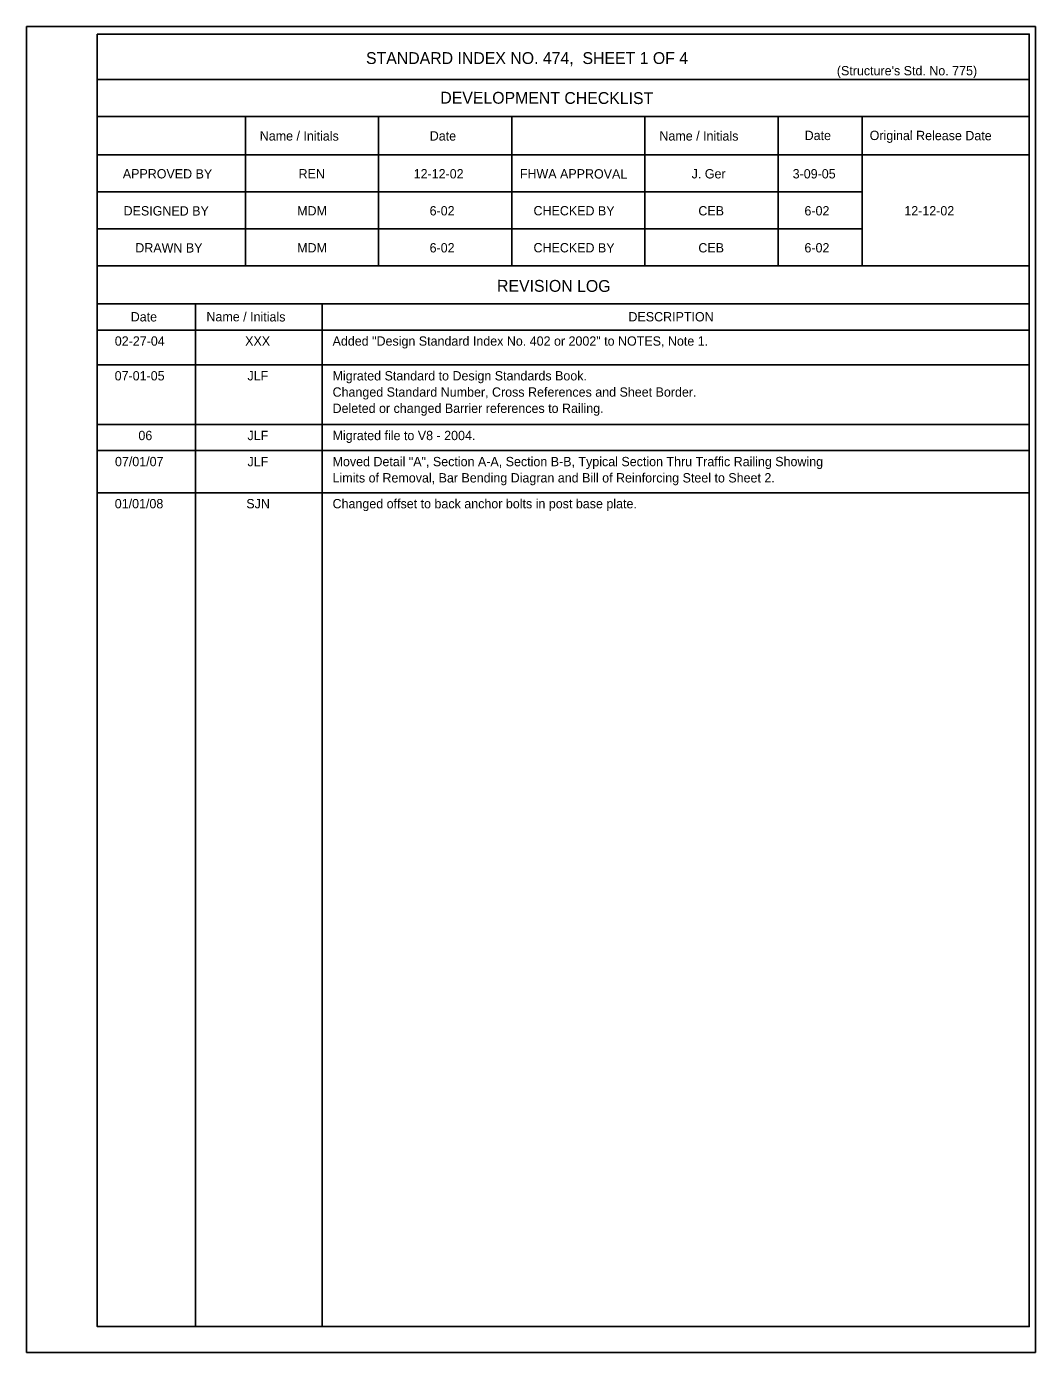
# Model space of a CAD drawing. Extents: x 21629.5 to 21698.8, y 56199.1 to 56237.6.
# Drawn here: x 21677.04 to 21698.85, y 56206.43 to 56235.1 of the extents above; entities that cross this region are included whole.
import ezdxf

# ---------------------------------------------------------------- set-up
doc = ezdxf.new("R2010")
doc.units = 0
for name, color, linetype in [('Border', 7, 'Continuous'), ('Dimension', 7, 'Continuous'), ('PlotBorder_dp', 7, 'Continuous'), ('TextStructures', 7, 'Continuous')]:
    doc.layers.add(name, color=color, linetype=linetype)

msp = doc.modelspace()

# ---------------------------------------------------------------- linework, layer by layer
at = {"layer": 'Border'}
for p, q in [((21698.712, 56233.957), (21678.566, 56233.957)), ((21698.712, 56233.157), (21678.566, 56233.157)), ((21681.766, 56233.157), (21681.766, 56229.929)), ((21684.646, 56233.157), (21684.646, 56229.929)), ((21687.526, 56233.157), (21687.526, 56229.929)), ((21690.406, 56233.157), (21690.406, 56229.929)), ((21693.286, 56233.157), (21693.286, 56229.929)), ((21695.101, 56233.157), (21695.101, 56229.929)), ((21698.712, 56232.329), (21678.566, 56232.329)), ((21695.101, 56231.529), (21678.566, 56231.529)), ((21695.101, 56230.729), (21678.566, 56230.729)), ((21698.712, 56229.929), (21678.566, 56229.929)), ((21698.712, 56229.102), (21678.566, 56229.102)), ((21680.686, 56229.102), (21680.686, 56206.995)), ((21683.428, 56229.102), (21683.428, 56206.995)), ((21698.712, 56228.538), (21678.566, 56228.538))]:
    msp.add_line(p, q, dxfattribs=at)
msp.add_lwpolyline([(21678.566, 56234.938), (21698.712, 56234.938), (21698.712, 56206.995), (21678.566, 56206.995)], close=True, dxfattribs=at)
at = {"layer": 'Dimension'}
for p, q in [((21678.566, 56227.787), (21698.712, 56227.787)), ((21678.566, 56226.496), (21698.712, 56226.496)), ((21678.566, 56225.932), (21698.712, 56225.932)), ((21678.566, 56225.022), (21698.712, 56225.022))]:
    msp.add_line(p, q, dxfattribs=at)
at = {"layer": 'PlotBorder_dp'}
msp.add_line((21677.035, 56206.434), (21677.035, 56206.434), dxfattribs=at)
msp.add_lwpolyline([(21677.035, 56235.1), (21698.848, 56235.1), (21698.848, 56206.434), (21677.035, 56206.434)], close=True, dxfattribs=at)

# ---------------------------------------------------------------- texts
at = {"layer": 'TextStructures'}
for s, height, p in [('STANDARD INDEX NO. 474,  SHEET 1 OF 4', 0.256, (21684.375, 56234.29)), ("(Structure's Std. No. 775)", 0.2016, (21694.554, 56234.045)), ('REN', 0.2016, (21682.917, 56231.816)), ('12-12-02', 0.2016, (21685.405, 56231.816)), ('J. Ger', 0.2016, (21691.415, 56231.816)), ('3-09-05', 0.2016, (21693.599, 56231.816)), ('MDM', 0.2016, (21682.886, 56231.016)), ('6-02', 0.2016, (21685.75, 56231.016)), ('CEB', 0.2016, (21691.56, 56231.016)), ('6-02', 0.2016, (21693.854, 56231.016)), ('12-12-02', 0.2016, (21696.013, 56231.016)), ('MDM', 0.2016, (21682.886, 56230.216)), ('6-02', 0.2016, (21685.75, 56230.216)), ('CEB', 0.2016, (21691.56, 56230.216)), ('6-02', 0.2016, (21693.854, 56230.216)), ('DESCRIPTION', 0.2016, (21690.049, 56228.725)), ('Added "Design Standard Index No. 402 or 2002" to NOTES, Note 1. ', 0.2016, (21683.652, 56228.2)), ('02-27-04', 0.2016, (21678.944, 56228.2)), ('XXX', 0.2016, (21681.762, 56228.2)), ('07-01-05', 0.2016, (21678.941, 56227.449)), ('JLF', 0.2016, (21681.812, 56227.449)), ('Migrated Standard to Design Standards Book.', 0.2016, (21683.652, 56227.449)), ('Changed Standard Number, Cross References and Sheet Border.', 0.2016, (21683.652, 56227.097)), ('Deleted or changed Barrier references to Railing.', 0.2016, (21683.652, 56226.746)), ('06', 0.2016, (21679.454, 56226.158)), ('JLF', 0.2016, (21681.813, 56226.158)), ('Migrated file to V8 - 2004.', 0.2016, (21683.652, 56226.158)), ('07/01/07', 0.2016, (21678.947, 56225.594)), ('JLF', 0.2016, (21681.813, 56225.594)), ('Moved Detail "A", Section A-A, Section B-B, Typical Section Thru Traffic Railing Showing ', 0.2016, (21683.652, 56225.594)), ('Limits of Removal, Bar Bending Diagran and Bill of Reinforcing Steel to Sheet 2.', 0.2016, (21683.652, 56225.243)), ('01/01/08', 0.2016, (21678.943, 56224.684)), ('SJN', 0.2016, (21681.787, 56224.684)), ('Changed offset to back anchor bolts in post base plate.', 0.2016, (21683.652, 56224.684))]:
    msp.add_text(s, height=height, dxfattribs=at).set_placement(p)
for s, height, p in [('DEVELOPMENT CHECKLIST', 0.256, (21685.981, 56233.434)), ('Name / Initials', 0.2016, (21682.078, 56232.636)), ('Date', 0.2016, (21685.753, 56232.635)), ('Name / Initials', 0.2016, (21690.718, 56232.636)), ('Date', 0.2016, (21693.858, 56232.646)), ('Original Release Date', 0.2016, (21695.264, 56232.646)), ('APPROVED BY', 0.2016, (21679.117, 56231.818)), ('FHWA APPROVAL', 0.2016, (21687.701, 56231.818)), ('DESIGNED BY', 0.2016, (21679.134, 56231.016)), ('CHECKED BY', 0.2016, (21687.996, 56231.018)), ('DRAWN BY', 0.2016, (21679.387, 56230.216)), ('CHECKED BY', 0.2016, (21687.996, 56230.218)), ('REVISION LOG', 0.256, (21687.207, 56229.368)), ('Date', 0.2016, (21679.288, 56228.725)), ('Name / Initials', 0.2016, (21680.925, 56228.727))]:
    msp.add_text(s, height=height, rotation=359.8756, dxfattribs=at).set_placement(p)

doc.saveas('drawing.dxf')
